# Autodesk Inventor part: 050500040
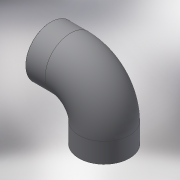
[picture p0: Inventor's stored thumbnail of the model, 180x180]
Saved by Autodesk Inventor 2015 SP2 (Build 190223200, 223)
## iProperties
Created: 2017-10
Part Number: 050500040
Material: Generic
Description: PLASSON 90° ELBOW-CEMENT PVC 40
Document SubType Name: Modeling
Designer: KIM
Density: 1 g/cm^3
Appearance: Default
Author: KIM
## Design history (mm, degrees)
derived "050500.ipt"
feature "Solid1::050500.ipt"
tag "TaggingFeature1"
body "Solid1"
other parameters: "d1" = 47, "d5" = 36, "d7" = 0.4, "d9" = 47, "d10" = 49.5, "d13" = 90 deg, "d18" = 23, "d19" = 90 deg, "d21" = 26, "d22" = 0, "d24" = 90 deg, "d26" = 36, "d27" = 90 deg, "E_" = 47, "H_" = 73, "l_" = 26, "Z_" = 23
